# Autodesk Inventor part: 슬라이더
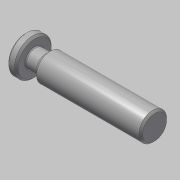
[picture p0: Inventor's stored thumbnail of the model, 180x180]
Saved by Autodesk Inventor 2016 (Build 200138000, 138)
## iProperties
Created: 2016-05
Part Number: 슬라이더
Document SubType Name: Modeling
Designer: mduedu
Density: 7.86 g/cm^3
Material: 강철, 연강
Appearance: 강철
Author: mduedu
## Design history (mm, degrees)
sketch "스케치1"
  geometry: L1 (-7.5, 0)-(62.5, 0); L2 (62.5, 0)-(62.5, 7.5); L3 (62.5, 7.5)-(0, 7.5); L4 (-7.5, 0)-(-7.5, 10); L5 (-7.5, 10)-(-2.5, 10); L6 (-2.5, 10)-(-2.5, 5); L7 (-2.5, 5)-(3.5, 5); L8 (3.5, 5)-(6, 7.5); A1 r 7.5 centre (0, 0) between (0, 7.5) and (-7.5, 0); 1 further point
  constraints: 16 end point, 3 perpendicular, 2 horizontal, 2 parallel, 2 point on circle, 2 point on line, 2 tangent, 1 centre point, 1 coincident
  dimensions: "d0" = 15 diameter of A1; "d1" = 70 distance of L1.start L1.end; "d19" = 20 diameter of L5 L1; "d20" = 10 diameter of L7 L1; "d21" = 5 distance of L4.end L5.end; "d22" = 135 deg angle of L8 L7; "d23" = 6 distance of L6.end L7.end
revolve "회전1" stored, may be unused: angle "d4" = 90 deg
chamfer "모따기2" distance "d24" = 1; stored, may be unused: second distance "d25" = 2, angle "d26" = 45 deg
fillet "모깎기1" dims "d27" = 0.5
node "솔리드1"
